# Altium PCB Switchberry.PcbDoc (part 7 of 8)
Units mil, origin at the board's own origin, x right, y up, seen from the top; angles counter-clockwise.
Board outline 4500 x 3824.8 mil, 6 copper layers (L01-TOP, L02-GND, L03-SIG, L04-SIG, L05-GND, L06-BOT), stack 49.214 mil thick; 431 components, 322 nets, 1699 pads, 1274 vias.
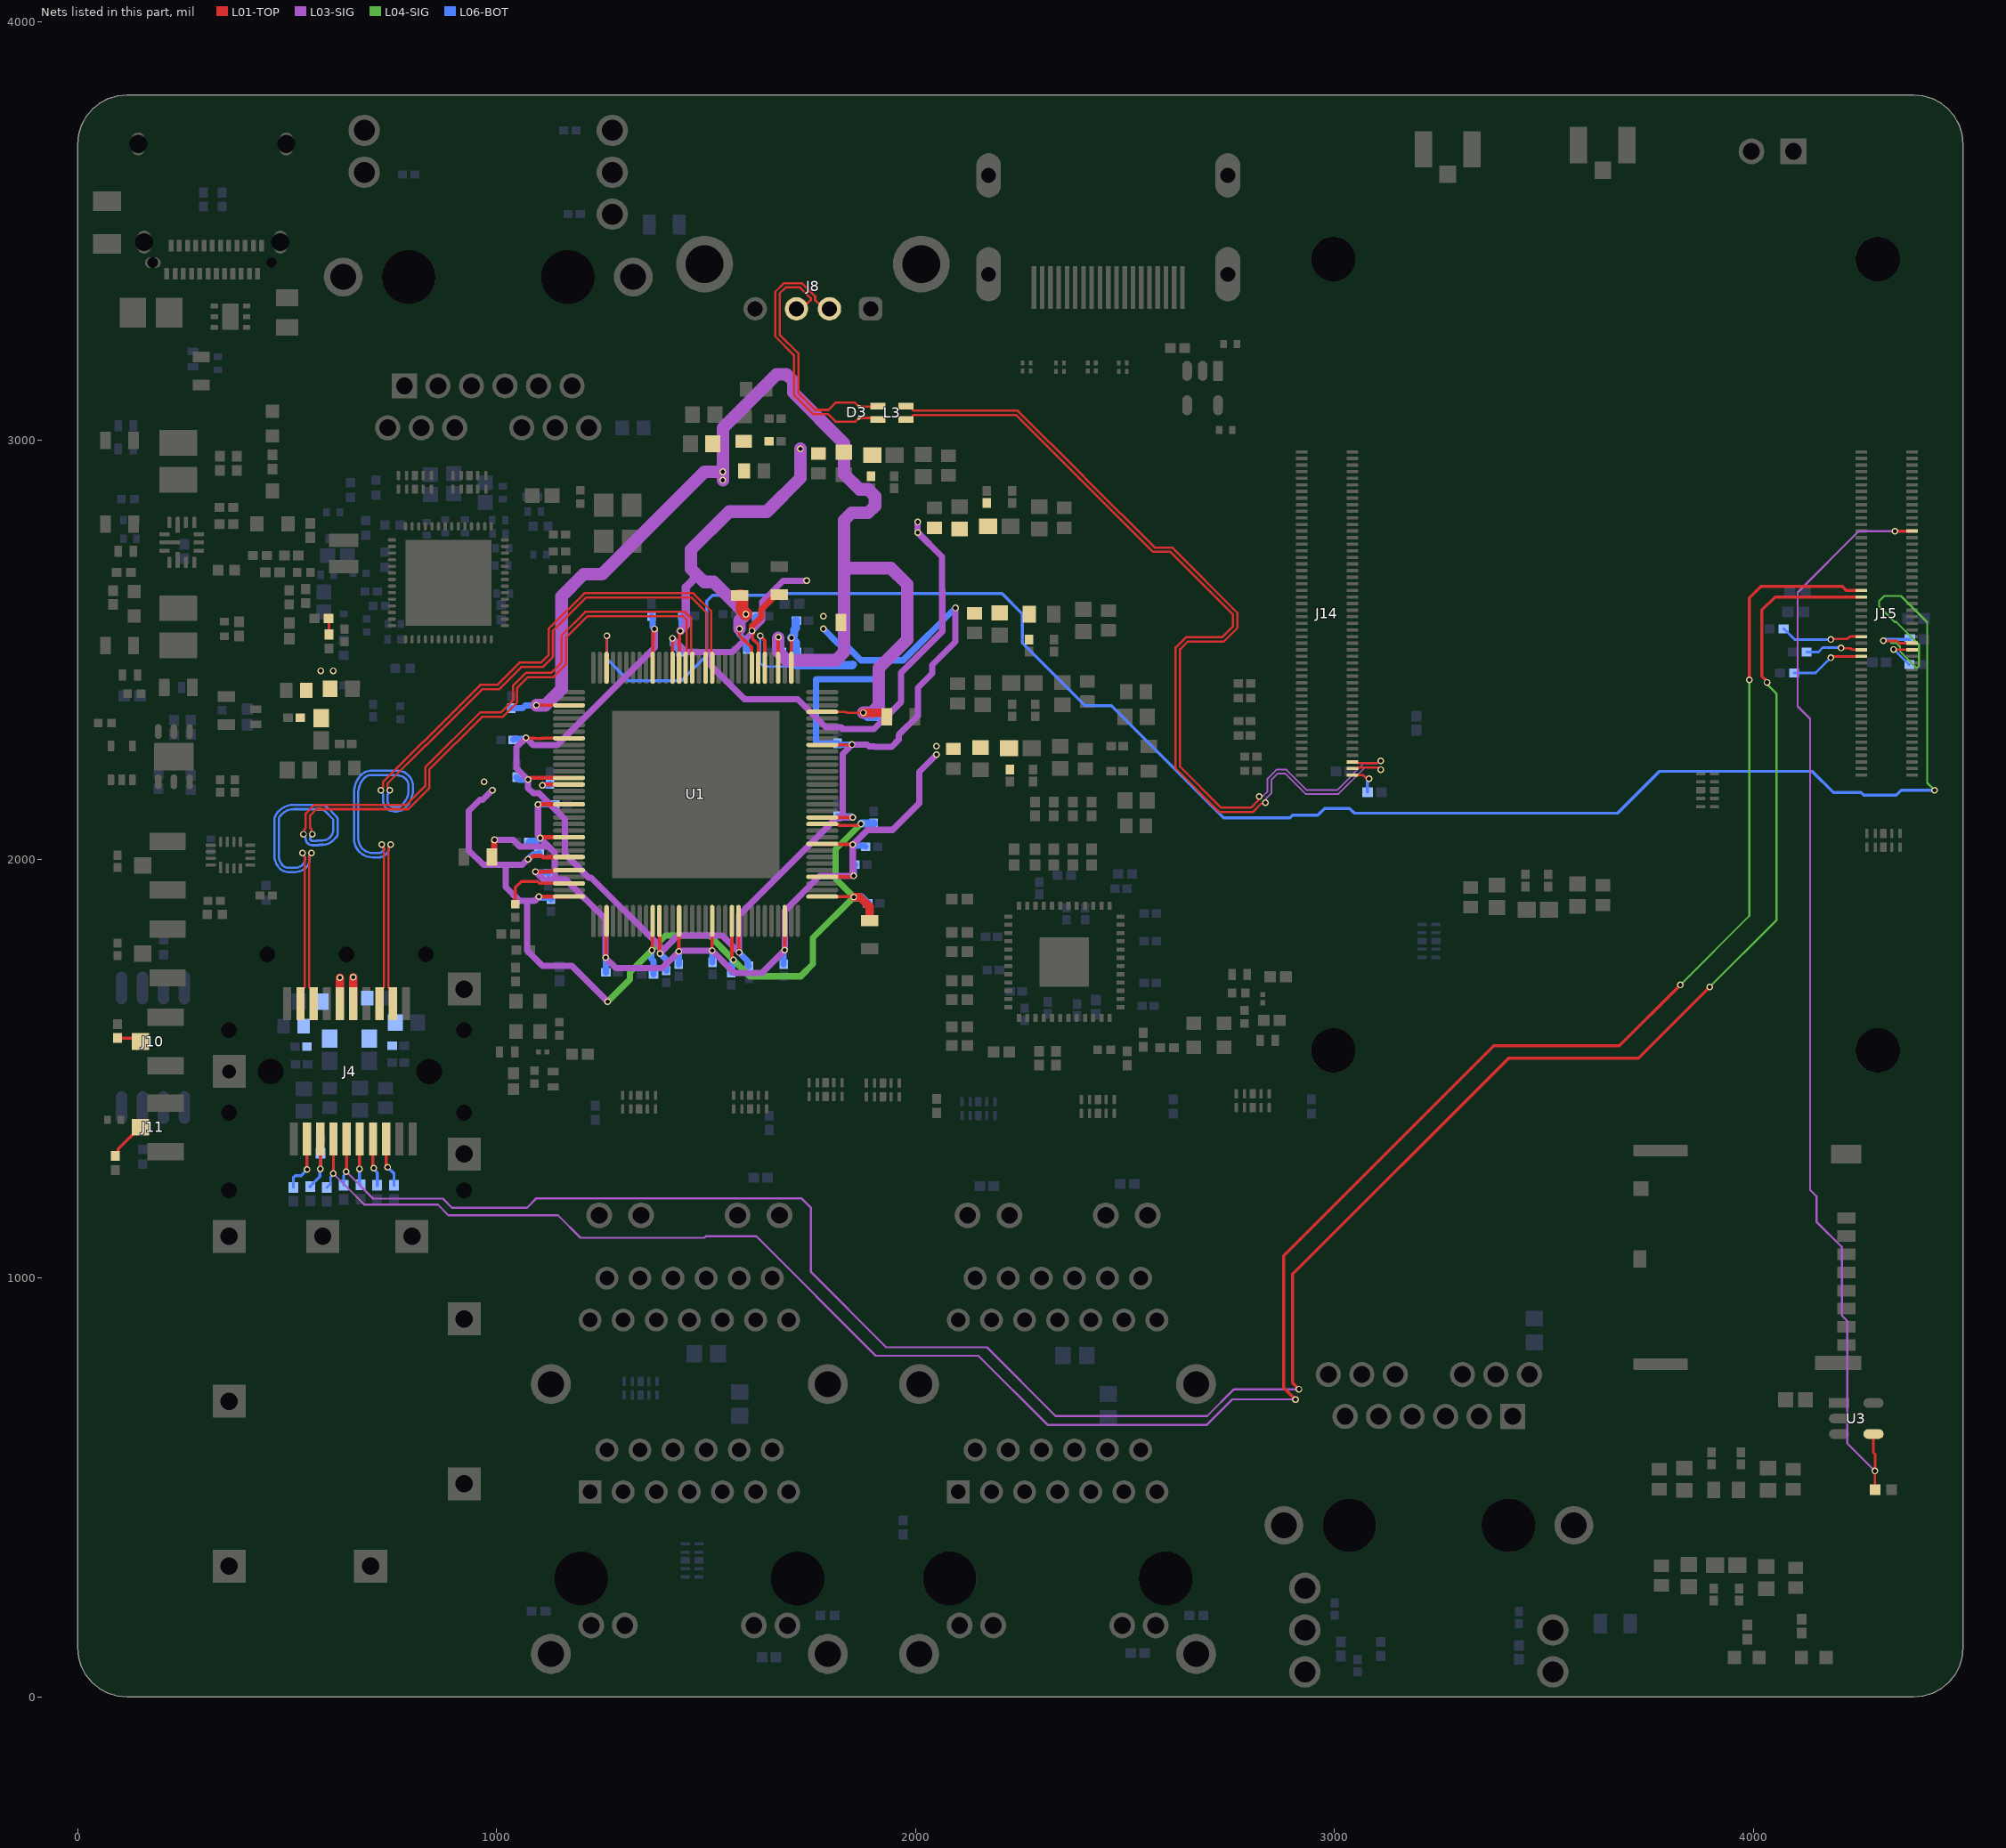
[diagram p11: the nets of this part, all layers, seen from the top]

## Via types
v1: diameter 16, hole 10, L01-TOP to L06-BOT, tented both sides, 1262 vias
v2: diameter 11.81, hole 7.87, L01-TOP to L06-BOT, tented both sides, 4 vias
v3: diameter 19.68, hole 7.87, L01-TOP to L06-BOT, tented both sides, 4 vias
v4: diameter 157.48, hole 110.24, L01-TOP to L06-BOT, tented both sides, 4 vias

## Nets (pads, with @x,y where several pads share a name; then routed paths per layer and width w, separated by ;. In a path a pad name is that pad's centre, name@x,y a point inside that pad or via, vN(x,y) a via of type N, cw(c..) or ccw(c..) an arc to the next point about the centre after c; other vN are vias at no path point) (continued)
SD_PWR_ON: J15.75 R28.1 U3.4 | length 2642.6
  L01-TOP w6: U3.4@4286.07,628.01 4286.07,583.93 4290,580 4290,540.27 v1(4289.54,539.82) 4289.54,495.77 R28.1@4290.31,495
  L01-TOP w7.27: v1(4337.32,2782.99) 4337.94,2783.6 J15.75@4377.9,2783.6
  L03-SIG w4.97: v1(4289.54,539.82) 4223.68,605.68 4223.68,897.64 4210.68,910.63 4210.68,1074.32 4150,1135 4150,1195.6 4135,1210.6 4135,2335 4105,2365 4105,2637.32 4250.66,2782.99 v1(4337.32,2782.99)
SFP1_FAULT: J4.2 R2.2 | length 136.8
  L01-TOP w7.27: J4.2@547.49,1332.05 547.49,1259.61 v1(547.72,1259.61)
  L06-BOT w7.27: R2.2@515,1216.73 515,1240 520,1245 533.12,1245 v1(547.72,1259.61)
SFP1_LOS: J4.8 R7.2 | length 120.1
  L01-TOP w7.27: J4.8@736.46,1332.05 736.46,1265 v1(740,1265)
  L06-BOT w7.27: v1(740,1265) 755,1250 R7.2@755,1221.73
SFP1_MOD_ABS: J4.6 R5.2 | length 110.8
  L01-TOP w7.27: v1(673,1261) 673,1332.05 J4.6@673.47,1332.05
  L06-BOT w7.27: v1(673,1261) 673,1224.76 R5.2@675.15,1222.61
SFP1_RATE_SELECT: J4.7 R6.2 | length 115.4
  L01-TOP w7.27: J4.7@704.97,1332.05 704.97,1262.53 v1(706.48,1262.53)
  L06-BOT w7.27: v1(706.48,1262.53) 706.48,1260.17 715,1251.65 R6.2@715,1221.73
SFP1_SCL: J4.5 J15.56 R4.2 | length 5553.9
  L01-TOP w7.27: v1(641.16,1254.13) 641.98,1254.13 J4.5@641.98,1332.05 ; v1(2915,735) 2900,750 2900,1009.49 3415.51,1525 3725,1525 v1(3895,1695) ; v1(4032,2422.28) 4032,2424.64 4020,2436.64 4020,2595 4051.06,2626.06 4256.58,2626.06 J15.56@4256.64,2626.12
  L03-SIG w4.97: v1(641.16,1254.13) 705.3,1189.99 871.87,1189.99 893.5,1168.36 1072.92,1168.36 1095.38,1190.82 1727.09,1190.82 1750.38,1167.53 1750.38,1014.49 1929.87,835 2170,835 2334.15,670.85 2695.85,670.85 2760,735 v1(2915,735)
  L04-SIG w4.97: v1(3895,1695) 4055,1855 4055,2395 4034.11,2415.89 4034.11,2420.17 v1(4032,2422.28)
  L06-BOT w6: R4.2@635,1221.73 635,1245.27 641.16,1251.43 v1(641.16,1254.13)
SFP1_SDA: J4.4 J15.58 R3.2 | length 5550
  L01-TOP w6: J15.58@4245.86,2642.8 4246.23,2642.77 J15.58@4256.64,2641.87
  L01-TOP w7.27: v1(610,1250) 610.48,1250 J4.4@610.48,1332.05 ; v1(2906.63,710) 2878.26,738.38 2878.26,1053.26 3380,1555 3680,1555 v1(3825,1700) ; v1(3990,2428.37) 3990,2623.37 4017.63,2651 4211.86,2651 4220.99,2641.87 J15.58@4256.64,2641.87
  L03-SIG w4.97: v1(610,1250) 684.53,1175.47 859.53,1175.47 885,1150 1146.54,1150 1200,1096.54 1496.23,1096.54 1500.18,1100.49 1619.51,1100.49 1905,815 2149.68,815 2314.68,650 2695,650 2755.84,710.84 2905.79,710.84 v1(2906.63,710)
  L04-SIG w4.97: v1(3825,1700) 3990,1865 v1(3990,2428.37)
  L06-BOT w6: R3.2@595,1216.73 603.81,1225.54 603.81,1241.1 610,1247.29 v1(610,1250)
SFP1_TXDISABLE: J4.3 R1.2 R8.1 | length 161.3
  L01-TOP w7.27: J4.3@578.98,1332.05 579.11,1332.05 v1(579.11,1261.07)
  L06-BOT w7.27: R1.2@555,1218.46 555,1219.45 577.71,1242.16 577.71,1259.67 v1(579.11,1261.07) 579.11,1297.38 R8.1@580,1298.27
SFP1_VCCR: C10.1 C11.2 C12.1 FB2.2 J4.15 | length 63.7
  L01-TOP w20: J4.15@657.72,1654.89 657.72,1718.37 v1(657.95,1718.37)
SFP1_VCCT: C4.1 C5.2 C6.1 FB1.2 J4.16 | length 62.8
  L01-TOP w20: J4.16@626.23,1654.89 v1@626.23,1717.64
  other v1: 626.19,1717.64
SFP_SW_N: J4.12 U1.78 | length 2155.5
  L01-TOP w5.38: v1(724,2165) 724,2167.87 729.31,2173.19 729.31,2185.37 825.02,2281.07 826.07,2281.07 961.17,2416.17 1001.17,2416.17 1054.4,2469.4 1105.73,2469.4 1123.98,2487.66 1123.98,2549.56 1209.8,2635.38 1469.3,2635.38 1511.69,2592.99 1511.69,2494.44 1514.37,2491.76 U1.78@1514.37,2457.18 ; v1(746.96,2035) cw(c740.03,2035) 744.93,2030.09 744.31,2029.47 ccw(c750.72,2023.06) 741.65,2023.06 741.65,1694.72 744.8,1691.57 745.06,1691.57 752.21,1684.42 J4.12@752.21,1654.89
  L06-BOT w5.38: v1(724,2165) ccw(c730.94,2165) 726.03,2160.09 cw(c718.12,2152.18) 729.31,2152.18 729.31,2138.82 ccw(c752.12,2138.82) 735.99,2122.69 ccw(c756.61,2143.25) 756.61,2114.14 761.43,2114.14 ccw(c761.43,2143.18) 781.97,2122.64 782,2122.68 ccw(c737.65,2167.04) 800.38,2167.04 800.38,2175.1 ccw(c766.09,2175.1) 799.45,2183.04 ccw(c766.09,2175.1) 790.34,2199.34 787.34,2202.34 ccw(c766.3,2181.3) 766.3,2211.05 698.68,2211.05 ccw(c698.68,2181.36) 677.68,2202.36 676.77,2201.45 ccw(c718.17,2160.05) 659.62,2160.05 659.62,2049.1 ccw(c704.03,2049.1) 672.63,2017.69 672.72,2017.6 ccw(c704.06,2048.94) 704.06,2004.62 719.25,2004.62 ccw(c719.25,2026.94) 735.03,2011.16 738.46,2014.59 ccw(c730.75,2022.3) 741.65,2022.3 741.65,2023.06 cw(c750.72,2023.06) 744.31,2029.47 v1@744.93,2030.09 ; v1@744.94,2030.1 ccw(c740.03,2035) v1(746.96,2035)
SFP_SW_P: J4.13 U1.79 | length 2022.8
  L01-TOP w5.38: J4.13@720.72,1654.89 720.72,1684.42 727.87,1691.57 728.13,1691.57 731.28,1694.72 731.28,2023.06 ccw(c722.21,2023.06) 728.62,2029.47 728,2030.09 cw(c732.9,2035) v1(725.96,2035) ; v1(745,2165) 745,2167.87 739.69,2173.19 739.69,2181.07 829.32,2270.7 830.37,2270.7 965.47,2405.79 1005.47,2405.79 1058.7,2459.02 1110.02,2459.02 1134.36,2483.36 1134.36,2545.26 1214.1,2625 1465,2625 1485,2605 1501.31,2588.69 1501.31,2494.44 1498.62,2491.76 U1.79@1498.62,2457.18
  L06-BOT w5.38: v1(725.96,2035) ccw(c732.9,2035) 727.99,2030.1 729.6,2028.49 cw(c725.56,2024.45) 731.28,2024.45 cw(c725.56,2024.45) 729.61,2020.42 727.73,2018.54 cw(c719.18,2027.09) 719.18,2015 704.14,2015 cw(c704.14,2049.14) 680,2025 cw(c704.14,2049.14) 670,2049.14 670,2160 cw(c718.28,2160) 684.14,2194.14 685,2195 cw(c698.7,2181.3) 698.7,2200.68 762.16,2200.68 cw(c762.16,2171.3) 782.93,2192.07 cw(c765.86,2175) 790,2175 790,2167.06 cw(c737.58,2167.06) 774.65,2130 cw(c761.4,2143.25) 761.4,2124.51 756.61,2124.51 cw(c756.61,2143.25) 743.36,2130 cw(c752.23,2138.87) 739.69,2138.87 739.69,2152.18 cw(c750.88,2152.18) 742.97,2160.09 ccw(c738.06,2165) v1(745,2165)
SPI0_CE0: J15.39 R44.2 | length 96.8
  L01-TOP w6: v1(4334,2501) 4334.43,2500.57 4377.46,2500.57 J15.39@4377.9,2500.13
  L06-BOT w6: v1(4334,2501) 4334.27,2501 4370.57,2464.7 R44.2@4371.55,2464.7
SPI0_CLK: J15.38 R45.1 | length 176.2
  L01-TOP w6: v1(4184,2481) 4187.39,2484.39 J15.38@4256.64,2484.39
  L06-BOT w6: R45.1@4096.73,2445 4148,2445 v1(4184,2481)
SPI0_MISO: J15.40 R47.1 | length 135.2
  L01-TOP w6: v1(4209,2504.39) ccw(c4212.03,2509.57) 4211.99,2503.57 4228.95,2503.57 cw(c4228.95,2497.57) 4232.65,2502.29 4233.22,2501.84 ccw(c4236.92,2506.57) 4236.92,2500.57 4245.86,2500.57 J15.40@4256.64,2500.13
  L06-BOT w6: R47.1@4126.73,2495 4155,2495 4165,2505 4208.39,2505 v1(4209,2504.39)
SPI0_MOSI: J15.44 R46.1 | length 197.9
  L01-TOP w6: v1(4184,2524.5) 4185.5,2526 4221.51,2526 ccw(c4221.51,2532) 4225.73,2527.73 ; 4225.74,2527.74 4227.89,2529.89 cw(c4232.12,2525.63) 4232.12,2531.63 J15.44@4256.64,2531.63
  L06-BOT w6: R46.1@4071.73,2550 4072.72,2550 4098.22,2524.5 v1(4184,2524.5)
SW_25MHz: C174.2 U1.126 | length 175.9
  L01-TOP w7.27: C174.2@1044.92,1893.04 1044.92,1933.13 1059.11,1947.32 1097.64,1947.32 1102.56,1942.4 U1.126@1172.82,1942.4
SW_AVDDH: C109.1 C110.2 C111.1 C112.1 C113.1 C114.1 C115.1 C116.1 C117.1 C118.1 C176.2 FB8.2 U1.10 U1.22 U1.33 U1.44 U1.111 U1.122 U1.128 | length 2783.8
  L01-TOP w5.38: v1(1370.49,1782.76) v1@1371.61,1783.89 ; U1.10@1371.61,1851.79 U1.10@1372.64,1852.82 ; v1@1851.46,1910.91 v1(1852.55,1909.81)
  L01-TOP w8: v1@1371.61,1783.89 U1.10@1371.61,1851.79 ; U1.22@1561.61,1852.82 1561.61,1766.26 1565,1762.87 v1(1565,1760) ; U1.33@1777.18,1910.91 v1@1851.46,1910.91 ; U1.44@1777.18,2084.13 1811.05,2084.13 1812.43,2082.75 1816.26,2082.75 1818.41,2080.6 1863.58,2080.6 1867.63,2084.64 v1(1869.79,2084.64)
  L01-TOP w10: v1(1075,2000) 1076.62,2000 1079.62,2003 1080.87,2003 1085.87,2008 1107.46,2008 1110.41,2005.05 1138.83,2005.05 1139.04,2005.25 1172.27,2005.25 U1.122@1172.47,2005.06 ; v1(1100.98,1910.56) 1101.32,1910.91 U1.128@1172.82,1910.91 ; v1(1109.35,2176.37) 1110.97,2176.37 1113.23,2178.62 U1.111@1172.82,2178.62
  L01-TOP w20: v1(1852.55,1909.81) 1867.12,1909.81 1890,1886.93 C176.2@1890,1853.46
  L03-SIG w15: v1(990,2165) 966.67,2141.67 959.92,2141.67 933.83,2115.58 933.83,2021.18 968.36,1986.65 1021.93,1986.65 ; v1(1075,2000) 1074.73,2000 1061.38,1986.65 1021.93,1986.65 ; v1(1100.98,1910.56) 1100.71,1910.56 1090.52,1900.37 1072.84,1900.37 ; v1(1265,1660) 1179.5,1745.5 1109.5,1745.5 1072.84,1782.16 1072.84,1900.37 ; 1021.93,1986.65 1021.93,1933.59 1055.15,1900.37 1072.84,1900.37
  L04-SIG w15: v1(1265,1660) 1317.74,1712.74 1317.74,1730.02 1370.68,1782.95 1370.68,1784.67 1403.51,1817.5 1508.04,1817.5 1536.43,1789.12 1536.43,1788.57 v1(1565,1760) 1604.39,1720.61 1725.61,1720.61 1755,1750 1755,1812.26 v1(1852.55,1909.81) 1808.9,1953.46 1808.9,2023.75 v1(1869.79,2084.64)
  L06-BOT w15: v1(1075,2000) 1075.27,2000 1087.69,2012.42 1098.64,2012.42 C117.1@1101.22,2015 ; v1(1100.98,1910.56) 1101.25,1910.56 1103.49,1908.33 1127.42,1908.33 1130,1905.75 C116.1@1130,1904.39 ; v1(1109.35,2176.37) 1109.54,2176.56 1124.95,2176.56 1127.53,2179.14 C118.1@1127.53,2179.98 ; v1(1370.49,1782.76) 1370.49,1782.49 1369.5,1781.5 1369.5,1762.47 1374.39,1757.58 C115.1@1374.39,1725 ; C114.1@1560,1729.39 1562.58,1731.97 1562.58,1757.31 1565,1759.73 v1(1565,1760)
  L06-BOT w20: v1(1852.55,1909.81) 1869.44,1909.81 1884.25,1895 C113.1@1885.61,1895 ; v1(1869.79,2084.64) 1870.76,2085.61 C112.1@1900,2085.61
  other v1: 970,2185 580,2450 610,2450
SW_AVDDL: C122.1 C123.2 C124.1 C125.1 C126.1 C127.1 C128.1 C129.1 C130.1 C131.1 C132.1 C133.1 C177.2 FB9.2 U1.3 U1.14 U1.19 U1.30 U1.36 U1.41 U1.114 U1.119 U1.124 | length 2862.2
  L01-TOP w5.38: v1(1260,1765) v1@1261.38,1766.38 ; U1.3@1261.38,1851.79 U1.3@1262.4,1852.82 ; v1(1435,1780) v1@1435.31,1780.31 ; U1.14@1435.31,1852.5 U1.14@1435.63,1852.82 ; v1@1514.37,1782.18 v1(1514.56,1781.99) ; v1(1687.47,1783.04) v1@1687.6,1783.16
  L01-TOP w8: v1@1261.38,1766.38 U1.3@1261.38,1851.79 ; v1@1435.31,1780.31 U1.14@1435.31,1852.5 ; v1@1514.37,1782.18 U1.19@1514.37,1852.82 ; v1@1687.6,1783.16 U1.30@1687.6,1852.82 ; U1.36@1777.18,1958.15 1850.22,1958.15 v1(1852.38,1960.31) ; U1.41@1777.18,2036.89 1778.13,2035.94 1849.06,2035.94 v1(1850,2035)
  L01-TOP w10: v1(1092.9,1970.15) 1129.96,1970.15 1133.33,1973.51 1139.11,1973.51 1139.49,1973.9 U1.124@1172.82,1973.9 ; v1(1098.77,2130.83) 1099.05,2131.1 1172.54,2131.1 U1.114@1172.82,2131.38 ; v1(1104.33,2050.72) 1105.95,2050.72 1107.87,2052.64 U1.119@1172.82,2052.64
  L01-TOP w15: C177.2@988.46,2005 993.76,2010.3 993.76,2044.79 995.04,2046.07 v1(995.04,2046.34)
  L03-SIG w15: v1(995.04,2046.34) 1039.5,2046.34 1055.09,2030.75 1124.31,2030.75 ; v1(1092.9,1970.15) 1093.17,1970.15 1111.98,1951.34 1138.74,1951.34 ; v1(1098.77,2130.83) 1098.77,2056.55 1104.33,2050.99 v1(1104.33,2050.72) 1124.31,2030.75 ; v1(2050,2250) 2008.81,2208.81 2008.81,2133.86 1945.18,2070.23 1885.23,2070.23 v1(1850,2035) 1850,1962.96 1852.38,1960.58 v1(1852.38,1960.31) 1771.07,1960.31 1687.67,1876.91 1687.67,1783.23 v1(1687.47,1783.04) 1633.32,1728.89 1567.12,1728.89 1535.96,1760.05 1535.96,1760.32 1514.56,1781.72 v1(1514.56,1781.99) 1437.26,1781.99 1435.27,1780 v1(1435,1780) 1394.87,1739.87 1285.13,1739.87 v1(1260,1765) 1260,1856.85 1165.5,1951.34 1138.74,1951.34 ; 1124.31,2030.75 1138.74,2016.31 1138.74,1951.34
  L06-BOT w5.38: C132.1@1070.55,2039.73 cw(c1074.45,2035.83) 1074.45,2041.34 C132.1@1076.64,2041.34
  L06-BOT w15: C132.1@1076.64,2041.34 1079.23,2043.92 1097.26,2043.92 1104.06,2050.72 v1(1104.33,2050.72) ; v1(1092.9,1970.15) 1093.17,1970.15 1094.24,1969.08 1120.92,1969.08 1123.5,1966.5 C131.1@1123.5,1965.14 ; v1(1098.77,2130.83) 1098.91,2130.96 1139.17,2130.96 C133.1@1139.31,2131.1 ; v1(1260,1765) 1260,1764.73 1260.61,1764.12 C130.1@1260.61,1730 ; C129.1@1435,1749.39 v1(1435,1780) ; v1(1514.56,1781.99) 1514.75,1781.8 1514.75,1754.64 C128.1@1515,1754.39 ; C127.1@1685,1749.39 1685,1780.29 1687.47,1782.77 v1(1687.47,1783.04) ; v1(1850,2035) 1850.27,2035 1852.69,2032.58 1878.03,2032.58 C125.1@1880.61,2030 ; v1(1852.38,1960.31) 1852.57,1960.5 1852.57,1984.38 1855.15,1986.96 C126.1@1855.39,1986.96
  other v1: 2050,2270
SW_DVDDL: C137.1 C138.2 C139.1 C140.1 C141.1 C142.1 C143.1 C144.1 C145.1 C146.1 C147.1 C148.1 C178.2 R93.2 U1.11 U1.23 U1.45 U1.56 U1.66 U1.70 U1.87 U1.104 U1.110 | length 4691.5
  L01-TOP w5.38: U1.11@1388.39,1852.82 U1.11@1389.19,1852.01 ; v1@1389.19,1775.81 v1(1390,1775) ; U1.23@1577.36,1852.82 U1.23@1578,1852.18 ; v1@1578,1778.28 v1(1578.64,1777.64)
  L01-TOP w8: v1(1070,2290) 1071.14,2288.86 1092.1,2288.86 1092.96,2288 1107.04,2288 1107.9,2288.86 U1.104@1172.82,2288.86 ; U1.87@1372.99,2457.54 1372.99,2526.83 1373.71,2527.55 1373.71,2541.18 1375.23,2542.69 1375.23,2548.34 v1(1376.76,2549.87) ; v1@1389.19,1775.81 U1.11@1389.19,1852.01 ; v1@1578,1778.28 U1.23@1578,1852.18 ; v1(1629.3,2533.7) 1629.3,2533.04 1640.32,2522.01 U1.70@1640.35,2457.18 ; U1.66@1703.35,2457.18 1703.51,2457.35 1703.51,2528.44 v1(1703.67,2528.6) ; U1.45@1777.18,2099.88 1777.24,2099.94 v1(1850,2100) v1(1850,2100) ; U1.56@1777.18,2273.11 1847.55,2273.11 v1(1848.19,2273.75)
  L01-TOP w10: v1(1075,2190) 1077.87,2190 1082.24,2194.37 U1.110@1172.82,2194.37
  L03-SIG w15: v1(1376.76,2549.87) 1377.21,2549.41 1377.21,2505.6 1144.69,2273.08 1087.19,2273.08 1070.27,2290 v1(1070,2290) 1047.51,2267.51 1047.51,2217.49 v1(1075,2190) 1075.19,2189.81 1075.19,2169.84 1087.34,2157.69 1100.9,2157.69 1163.52,2095.07 1163.52,2012.58 1219.77,1956.32 1225.91,1956.32 1390.99,1791.25 1390.99,1776.26 1390,1775.27 v1(1390,1775) 1432.5,1817.5 1538.78,1817.5 v1(1578.64,1777.64) 1578.64,1866.18 1812.46,2100 1829.49,2100 ; v1@1849.81,2099.81 v1(1850,2100) 1829.49,2100 ; v1(2095,2600) 2095,2519.29 2039.5,2463.79 2039.5,2444.05 2005.45,2410 2005.45,2343.12 1959.83,2297.5 1959.83,2285.84 1942.6,2268.61 1902.44,2268.61 1901.61,2269.44 1888.54,2269.44 1884.23,2273.75 v1(1848.19,2273.75) 1826.13,2251.69 1826.13,2103.36 1829.49,2100
  L06-BOT w5.38: v1(1629.3,2533.7) 1629.3,2468.24 1638.11,2459.43 1642.57,2459.43 1643.14,2460 1715.61,2460
  L06-BOT w15: C141.1@1039.39,2285 1041.97,2287.58 1067.31,2287.58 1069.73,2290 v1(1070,2290) ; C148.1@1047.51,2196.19 1047.51,2194.84 1050.09,2192.25 1051.45,2192.25 1053.51,2190.19 1074.81,2190.19 v1(1075,2190) ; C142.1@1370,2580.61 1370,2579.25 1372.58,2576.67 1372.58,2554.31 1376.76,2550.14 v1(1376.76,2549.87) ; v1(1390,1775) 1405,1760 C147.1@1405,1734.39 ; v1(1578.64,1777.64) 1578.64,1777.37 1599.43,1756.58 1599.43,1747.25 C146.1@1602.01,1744.67 ; v1(1780,2550) 1814.64,2515.36 1829.57,2515.36 1869.93,2475 1970,2475 v1(2095,2600) ; C145.1@1813.74,2102.89 1846.83,2102.89 1849.73,2100 v1(1850,2100) ; v1(1848.19,2273.75) 1848,2273.95 1816.68,2273.95 1814.1,2276.53 C144.1@1814.1,2276.9 1761.98,2276.9 1761.98,2430 1920,2430 1920,2455
  L06-BOT w20: C140.1@1715.61,2570 1714.25,2570 1714.17,2569.92 1714.17,2551.7 1710.23,2547.76 1710.23,2535.16 v1(1703.67,2528.6) 1714.17,2518.11 1714.17,2495.08 1714.25,2495 C143.1@1715.61,2495 1715.61,2463.49 1848.49,2463.49 1850,2465
  other v1: 1780,2580
SW_GPIO_1: J10.1 R49.2 | length 58.4
  L01-TOP w7.27: R49.2@95,1573.27 141.69,1573.27 J10.1@149.96,1565
SW_INTR_N: J15.41 R41.1 U1.94 | length 4841.8
  L01-TOP w6: U1.94@1262.4,2457.18 1262.4,2532.9 v1(1263.01,2533.51) ; v1(4309.51,2521.51) 4310.01,2521 4342.28,2521 4347.4,2515.88 J15.41@4377.9,2515.88
  L04-SIG w4.97: v1(4309.51,2521.51) 4324.06,2521.51 4329.08,2516.49 4340.41,2516.49 4349.49,2507.41 4349.49,2496.08 4387.27,2458.3 4391.39,2458.3 4394.3,2461.21 4394.3,2512.6 4340.41,2566.49 4336.62,2566.49 4299.51,2603.59 4299.51,2616.41 4311.59,2628.49 4351.41,2628.49 4414.24,2565.66 4414.24,2182.48 v1(4431.72,2165)
  L06-BOT w7.27: v1(1263.01,2533.51) 1263.01,2477.83 1315.01,2425.83 1441.27,2425.83 1498.62,2483.18 ; 1502.11,2486.67 1498.62,2483.18 ; v1(4309.51,2521.51) 4311.87,2521.51 4315.36,2525 R41.1@4373.27,2525 ; v1(4431.72,2165) 4351.81,2165 4340.19,2153.38 4262.64,2153.38 4256.22,2159.8 4190.2,2159.8 4140,2210 3775,2210 3675,2110 3047.65,2110 3036.01,2121.63 2976.32,2121.63 2959.69,2105 2900,2105 2893.76,2098.76 2735.35,2098.76 2467.48,2366.63 2404.84,2366.63 2255.2,2516.28 2255.2,2585.69 2206.49,2634.4 1675.85,2634.4 1671.45,2630 1515,2630 1501.31,2616.31 1501.31,2485.87 1498.62,2483.18
SW_RST_N: R43.2 R75.1 | length 38.8
  L01-TOP w7.27: R75.1@598.93,2575.09 600,2574.03 R43.2@600,2536.73
SW_SFP_N: J4.19 U1.82 | length 2165.9
  L01-TOP w5.38: J4.19@531.74,1654.89 531.74,1684.42 538.89,1691.57 539.15,1691.57 542.3,1694.72 542.3,1758.16 542.3,2003.06 ccw(c533.23,2003.06) 539.64,2009.47 539.02,2010.09 cw(c543.93,2015) v1(536.99,2015) ; v1(560.31,2060) 558.28,2062.03 558.28,2071.72 555,2075 555,2105 569.62,2119.62 789.3,2119.62 840,2170.32 840,2215 965,2340 1014.61,2340 1049.31,2374.7 1049.31,2409.63 1074.68,2435 1135.28,2435 1165.38,2465.1 1165.38,2529.12 1216.26,2580 1445,2580 1454.06,2570.94 1454.06,2494.44 1451.38,2491.76 U1.82@1451.38,2457.18
  L06-BOT w5.38: v1(536.99,2015) ccw(c543.93,2015) 539.02,2010.09 539.64,2009.47 cw(c533.23,2003.06) 542.3,2003.06 542.3,1999.56 cw(c524.78,1999.56) 537.17,1987.17 537.07,1987.07 cw(c520,2004.14) 520,1980 502.07,1980 cw(c502.07,1997.07) 490,1985 cw(c514.14,2009.14) 480,2009.14 480,2092.93 cw(c497.07,2092.93) 485,2105 488.75,2108.75 cw(c515,2082.5) 515,2119.62 580.38,2119.62 cw(c580.38,2107.56) 588.91,2116.09 610,2095 610,2071.21 cw(c582.93,2071.21) 602.07,2052.07 cw(c585,2069.14) 585,2045 572.69,2045 ccw(c572.69,2043.18) 571.4,2044.47 cw(c570.11,2045.75) 570.11,2043.93 560.38,2043.93 cw(c560.38,2049.31) 556.58,2045.51 cw(c560.38,2049.31) 555,2049.31 555,2049.45 cw(c560.71,2049.45) 556.66,2053.48 558.28,2055.09 ccw(c553.37,2060) v1(560.31,2060)
SW_SFP_P: J4.18 U1.81 | length 2299.7
  L01-TOP w5.38: v1(539.31,2060) 541.34,2062.03 541.34,2071.72 544.62,2075 544.62,2109.3 565.32,2130 785,2130 829.62,2174.62 829.62,2219.3 960.7,2350.38 1010.31,2350.38 1038.93,2379 1038.93,2413.93 1070.38,2445.38 1130.98,2445.38 1155,2469.4 1155,2533.42 1211.96,2590.38 1449.3,2590.38 1452.34,2587.34 1464.44,2575.24 1464.44,2494.44 1467.13,2491.76 U1.81@1467.13,2457.18 ; v1(557.99,2015) cw(c551.05,2015) 555.96,2010.09 555.33,2009.47 ccw(c561.74,2003.06) 552.68,2003.06 552.68,1753.86 552.68,1694.72 555.83,1691.57 556.08,1691.57 563.24,1684.42 J4.18@563.24,1654.89
  L06-BOT w5.38: v1(539.31,2060) ccw(c546.25,2060) 541.34,2055.09 541.43,2055.01 cw(c533.72,2047.3) 544.62,2047.3 ccw(c555.52,2047.3) 547.81,2039.6 549.24,2038.17 ccw(c560.38,2049.31) 560.38,2033.56 574.41,2033.56 ccw(c574.41,2035.38) 575.7,2034.09 cw(c576.98,2032.8) 576.98,2034.62 585.07,2034.62 ccw(c585.07,2068.98) 609.36,2044.68 617.34,2052.66 ccw(c610,2060) 620.38,2060 620.38,2095.04 ccw(c610.1,2095.04) 617.37,2102.31 ; v1(557.99,2015) cw(c551.05,2015) 555.96,2010.09 555.33,2009.47 ccw(c561.74,2003.06) 552.68,2003.06 552.68,1995.55 cw(c534.45,1995.55) 547.34,1982.66 544.41,1979.73 cw(c520,2004.14) 520,1969.62 502.07,1969.62 cw(c502.07,1997.07) 482.66,1977.66 cw(c514.14,2009.14) 469.62,2009.14 469.62,2092.99 cw(c496.92,2092.99) 477.62,2112.3 481.44,2116.12 cw(c514.95,2082.61) 514.95,2130 580.46,2130 cw(c580.46,2107.76) 596.19,2123.49 617.37,2102.31
SW_VDDHS: C152.1 C153.2 C154.1 C155.1 C156.1 C179.2 FB10.2 U1.72 U1.83 | length 1158.8
  L01-TOP w8: U1.83@1436.13,2457.69 1436.13,2519.81 1436.82,2520.5 v1@1436.82,2537.79 ; v1@1436.84,2537.81 1436.84,2543.47 v1(1438.37,2545) ; v1(1579.63,2550.09) 1580.22,2549.5 1580.22,2534.03 1608.86,2505.38 U1.72@1608.86,2457.18
  L01-TOP w30: C179.2@1580,2630 1583.46,2630 1585.67,2627.8 1585.67,2594.33 v1(1595,2585)
  L03-SIG w20: v1(1438.37,2545) 1451.39,2558.01 1451.39,2649.4 1479.8,2677.8
  L03-SIG w30: v1(1579.63,2550.09) 1579.63,2569.63 v1(1595,2585) 1518.06,2661.94 1495.66,2661.94 1479.8,2677.8 1463.93,2693.67 1463.93,2738.93 1555,2830 1645,2830 1725,2910 v1(1725,2980)
  L06-BOT w15: v1(1438.37,2545) 1438.37,2545.27 1441.81,2548.71 1441.81,2579.1 C156.1@1444,2581.29 ; v1(1579.63,2550.09) 1579.5,2549.97 1579.5,2536.51 1595.45,2520.56 1595.45,2502.58 1598.03,2500 C155.1@1599.39,2500
SW_VDDIO: C168.1 C169.2 C170.1 C171.1 C172.1 C173.1 C181.2 R94.2 U1.61 U1.68 U1.99 | length 3136.9
  L01-TOP w5.38: v1(1095,2367.76) v1@1095.08,2367.68 ; U1.99@1172.74,2367.68 U1.99@1172.82,2367.6 ; U1.61@1777.18,2351.85 1834.03,2351.85 1835.88,2350 v1(1875,2350)
  L01-TOP w8: v1@1095.08,2367.68 U1.99@1172.74,2367.68 ; U1.68@1671.85,2457.18 1672.07,2457.41 1672.07,2529.78 v1(1672.3,2530)
  L01-TOP w20: v1(1875,2350) 1928.74,2350 1931.54,2347.2 C181.2@1931.54,2340
  L03-SIG w30: v1(1095,2367.76) 1116.61,2367.76 1155,2406.15 1155,2627.51 1207.97,2680.49 1251.73,2680.49 1496.24,2925 v1(1540,2925) ; v1(1540,2905) v1(1540,2925) ; v1@1672.36,2528.14 1672.07,2527.85 1672.07,2495.45 1692.52,2475 1810,2475 1829.57,2494.57 1829.57,2695 ; v1@1875.22,2350.17 1875.39,2350 1895.13,2350 1912.22,2367.09 1912.22,2456.6 1980.33,2524.71 1980.33,2655.86 1941.19,2695 1829.57,2695 ; v1(1540,2925) 1540,3029.6 1668.4,3158 1691.6,3158 1708,3141.6 1708,3113.93 1829.57,2992.36 1829.57,2920.03 1866.6,2883 1886.6,2883 1903,2866.6 1903,2843.4 1886.6,2827 1847.14,2827 1829.57,2809.43 1829.57,2695
  L06-BOT w15: C172.1@1035,2360.61 1061.62,2360.61 1068.57,2367.56 1094.81,2367.56 v1(1095,2367.76) ; v1(1672.3,2530) 1677.95,2524.34 1677.95,2495.08 1678.03,2495 C173.1@1679.39,2495
  L06-BOT w20: v1(1875,2350) 1884.92,2340.08 1905.53,2340.08 C171.1@1905.61,2340
SW_VDDLS: C160.1 C161.2 C162.1 C163.1 C164.1 C180.2 FB11.2 U1.71 U1.84 | length 1867.7
  L01-TOP w5.38: v1(1609.35,2545.65) v1@1610.66,2544.34
  L01-TOP w8: U1.84@1419.88,2457.18 v1@1419.85,2527.51 ; v1@1610.66,2544.34 1610.66,2526.89 1624.61,2512.95 U1.71@1624.61,2457.18
  L01-TOP w15: v1(1609.35,2545.65) 1609.54,2545.84 1609.54,2556.38 1632.05,2578.88 1632.05,2596.46 1667.13,2631.54 C180.2@1675,2631.54
  L03-SIG w15: v1(1419.82,2527.54) 1452.92,2494.44 1513.03,2494.44 ; v1(1740,2665) 1683.62,2665 1633.66,2615.04 1633.66,2569.96 v1(1609.35,2545.65) 1609.16,2545.46 1609.16,2540.73 1562.87,2494.44 1513.03,2494.44 ; v1(2005,2805) v1(2005,2780) 2062.63,2722.37 2062.63,2644.69 2063.49,2643.83 2063.49,2543.49 1965.67,2445.67 1965.67,2375.85 1900.55,2310.73 1826.61,2310.73 1822.44,2314.9 1786,2314.9 1718.75,2382.15 1591.77,2382.15 1513.03,2460.9 1513.03,2494.44
  L06-BOT w15: v1(1419.82,2527.54) 1420.01,2527.35 1420.01,2512.74 1438.31,2494.44 C163.1@1439.67,2494.44 ; v1(1609.35,2545.65) 1609.54,2545.84 1609.54,2546.61 1616.67,2553.74 1616.67,2577.42 1619.25,2580 C164.1@1620.61,2580
SYNCLKO: J11.1 R48.1 | length 105.4
  L01-TOP w7.27: R48.1@90,1291.73 97.19,1298.92 97.19,1308.22 148.98,1360 J11.1@149.96,1360 J11.1@141.69,1351.73
USB_FILT_N: D3.2 J8.2 L3.1 | length 664.7
  L01-TOP w5.38: J8.2@1794.37,3314.17 1780.99,3314.17 1760.19,3334.98 1760.19,3343.73 1728.54,3375.38 1685.7,3375.38 1665.15,3354.83 1665.15,3248.27 1709.62,3203.81 1709.62,3108.39 1755.7,3062.31 1791.62,3062.31 1808.93,3045 1856.38,3045 D3.2@1864.94,3053.56 1906.44,3053.56 L3.1@1910,3050
USB_FILT_P: D3.3 J8.3 L3.4 | length 612.6
  L01-TOP w5.38: J8.3@1715.63,3314.17 1729.01,3314.17 1749.81,3334.98 1749.81,3339.43 1724.24,3365 1690,3365 1675.53,3350.53 1675.53,3252.57 1720,3208.1 1720,3112.69 1760,3072.69 1791.62,3072.69 1808.93,3090 1855.27,3090 D3.3@1864.94,3080.33 1908.84,3080.33 L3.4@1910,3081.5
USB_N: J14.3 L3.2 | length 2172
  L01-TOP w5.38: L3.2@1976.93,3050 1986.77,3050 1991.96,3055.19 1991.96,3057.41 1995.11,3060.56 2239.44,3060.56 2390,2910 2566.17,2733.83 2607.73,2733.83 2757.56,2584 2757.56,2556.65 2730.91,2530 2645.32,2530 2620.66,2505.34 2620.66,2216.79 2721.91,2115.55 2724.95,2112.51 2804.69,2112.51 2825.31,2133.12 2832.82,2133.12 v1(2834.85,2135.15) ; J14.3@3042.46,2216.67 3052.31,2216.67 3054.99,2219.35 3101.81,2219.35 3107.13,2214.04 v1(3110,2214.04)
  L03-SIG w4.04: v1(2834.85,2135.15) 2836.52,2136.83 2836.52,2145.28 2849.04,2157.8 2849.04,2189.04 2865,2205 2881.43,2205 2903.49,2182.95 2930.48,2155.96 3009.38,2155.96 3073.44,2220.02 3101.65,2220.02 3107.63,2214.04 v1(3110,2214.04)
USB_OTG: J14.1 R9.2 | length 76.9
  L01-TOP w6: J14.1@3042.46,2200.92 3068.47,2200.92 3077.13,2192.26 v1(3082,2192.26)
  L06-BOT w7.27: R9.2@3078.27,2160 3078.27,2186.16 3082,2189.9 v1(3082,2192.26)
USB_P: J14.5 L3.3 | length 2170.9
  L01-TOP w5.38: L3.3@1976.93,3081.5 1986.77,3081.5 1991.96,3076.31 1991.96,3074.09 1995.11,3070.94 2243.74,3070.94 2397.34,2917.34 2407.61,2907.07 2570.47,2744.21 2612.03,2744.21 2767.94,2588.3 2767.94,2552.35 2735.21,2519.62 2649.62,2519.62 2631.04,2501.04 2631.04,2221.09 2729.25,2122.88 2800.4,2122.88 2817.97,2140.46 2817.97,2147.97 v1(2820,2150) ; J14.5@3042.46,2232.42 3052.31,2232.42 3054.99,2229.73 3101.81,2229.73 3107.13,2235.04 v1(3110,2235.04)
  L03-SIG w4.04: v1(2820,2150) 2821.68,2151.68 2830.13,2151.68 2840,2161.55 2840,2192.79 2861.25,2214.04 2885.18,2214.04 2934.22,2165 3005.63,2165 3069.7,2229.07 3101.65,2229.07 3107.63,2235.04 v1(3110,2235.04)
pads on no net: J1. J2. J3. J4.MH1 J4.MH2 J7.14 J9. J9.A2 J9.A3 J9.A6 J9.A7 J9.A8 J9.A10 J9.A11 J9.B2 J9.B3 J9.B6 J9.B7 J9.B8 J9.B10 J9.B11 J14.4 J14.6 J14.11 J14.15 J14.17 J14.21 J14.23 J14.27 J14.28 J14.29 J14.30 J14.33 J14.34 J14.35 J14.36 J14.39 J14.40 J14.41 J14.42 J14.43 J14.45 J14.46 J14.47 J14.48 J14.49 J14.52 J14.54 J14.57 J14.58 J14.59 J14.60 J14.63 J14.64 J14.65 J14.66 J14.69 J14.71 J14.75 J14.77 J14.81 J14.83 J14.87 J14.89 J14.93 J14.94 J14.95 J14.96 J15.20 J15.29 J15.30 J15.31 J15.34 J15.35 J15.36 J15.37 J15.46 J15.48 J15.49 J15.64 J15.68 J15.70 J15.72 J15.73 J15.76 J15.80 J15.82 J15.89 J15.91 J15.92 J15.94 J15.96 J15.99 J15.100 J17. SD1.9 SD1.10 U1.50 U1.51 U1.59 U1.60 U1.73 U1.74 U1.93 U1.108 U1.125 U3.3 U4.13 U4.43 U4.45 U4.47 U23.3@935,2883.56 U23.8@935,2916.44 U24.3@805,2883.56 U24.8@805,2916.44

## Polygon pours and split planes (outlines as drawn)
SW_AVDDH on L04-SIG "NONET_L-01_P-001" (solid, remove dead copper, pour order 86): 1249.51,1684.51 1422.53,1857.53 1612.53,1857.53 1655,1900 1655,2022.01 1780.12,2147.13 1876.59,2147.13 1894.02,2129.7 1894.02,1690.43 1846.59,1643 1257,1643 1249.51,1650.49
SW_AVDDH on L04-SIG "NONET_L-01_P-001" (solid, remove dead copper, pour order 10): 533.26,2484.56 533.26,2291.74 743.55,2081.45 1124.35,2081.45 1156.48,2113.58 1156.48,2237.73 1139.21,2255 935,2255 705,2485 637.39,2485
P3V3 on L04-SIG "NONET_L-01_P-001" (solid, remove dead copper, pour order 40): 1601.79,2844.62 1881.23,2844.62 2005.38,2720.47 2875.13,2720.47 4182.28,2720.47 4182.28,2930 2450.32,2930 2185.32,3195 1600,3195
P3V3 on L04-SIG "NONET_L-01_P-001" (solid, remove dead copper, pour order 70): 565,2903.43 875.7,3214.13 1700.87,3214.13 1775,3140 1775,2865 1754.62,2844.62 1310.18,2844.62 925.89,2460.33 665,2460.33 665,2453.58 638.24,2426.83
P3V3 on L04-SIG "NONET_L-01_P-001" (solid, remove dead copper, pour order 61): 953.96,1340 3845,1340 4381.89,803.11 4381.89,456.89 3990,65 391.25,65 208.25,248
P3V3 on L04-SIG "NONET_L-01_P-001" (solid, remove dead copper, pour order 60): 675,2255 1172.71,2255 1172.71,1285 652.72,1285 652.72,1374.63
P3V3 on L04-SIG "NONET_L-01_P-001" (solid, remove dead copper, pour order 59): 675,2505 675,2255 985.38,1944.62 985.38,255.38 855,125 330,125 52.49,402.51 52.49,2456.81 194.6,2598.92
P3V3 on L04-SIG "NONET_L-01_P-001" (solid, remove dead copper, pour order 58): 110,2514.32 194.6,2598.92 363.92,2598.92 530,2765 530,2890 550,2910 675,2910 800,2785 800,2545 760,2505 675,2505 675,2345 635,2305 140,2305 110,2335
P5V on L04-SIG "NONET_L-01_P-001" (solid, remove dead copper, pour order 57): 235,3267.5 235,3625.97 316.55,3707.52 3877.48,3707.52 4425,3160 4425,2776 4059.95,2776 3805.95,3030 2925,3030 2858.65,2963.65 2466.35,2963.65 2220.37,3209.63 889.63,3209.63 620,2940 490,2940
P5V on L04-SIG "NONET_L-01_P-001" (solid, remove dead copper, pour order 56): 235,3267.5 235,3035 125,2925 125,2683.41 194.6,2613.81 371.54,2613.81 513.91,2756.18 513.91,3464.25 394.09,3464.25
P5V on L04-SIG "NONET_L-01_P-001" (solid, remove dead copper, pour order 54): 235,3464.96 423.62,3464.96 423.62,3235 235,3235 235,3300
CHASSIS_GND on L04-SIG "NONET_L-01_P-001" (solid, remove dead copper, pour order 53): 3530,1110 3695,945 3695,165 3600,70 995,70 995,1110
GND on L02-GND "NONET_L-01_P-001" (solid, remove dead copper, pour order 12): -145,3870 4620,3870 4620,-90 -140,-90 -140,3615
GND on L05-GND "NONET_L-01_P-001" (solid, remove dead copper, pour order 11): -145,3870 4620,3870 4620,-90 -140,-90 -140,3615
P0V95_I225 on L01-TOP "NONET_L-01_P-001" (solid, remove dead copper, pour order 14): 599.57,2761.5 599.57,2817.12 603.44,2820.99 647.99,2820.99 670.43,2798.55 670.43,2761.5
SW_DVDDL on L01-TOP "NONET_L-01_P-001" (solid, remove dead copper, pour order 17): 1834.33,2595.67 1820,2610 1770,2610 1765,2605 1765,2543.62 1783.62,2525 1820,2525 1834.33,2539.33 1834.33,2544.33
GND on L01-TOP "NONET_L-01_P-001" (solid, remove dead copper, pour order 96): -105,1060 -105,3765 35,3905 4535,3905 4645,3795 4645,-30 4575,-100 4555,-80 -110,-80
P2V5 on L01-TOP "NONET_L-01_P-001" (solid, remove dead copper, pour order 95): 438.12,2330.65 463.77,2305 570,2305 580,2295 580,2250 575,2245 400,2245 380,2265
PHY_DVDDL on L01-TOP "NONET_L-01_P-001" (solid, remove dead copper, pour order 93): 2484.25,2220.08 2490.39,2226.22 2603.78,2226.22 2640,2190 2640,2070 2632.28,2062.28 2535.16,2062.28 2535.16,2166.42 2521.58,2180 2500,2180 2500,2184.17 2484.25,2199.92
P1V2 on L01-TOP "NONET_L-01_P-001" (solid, remove dead copper, pour order 77): 2535.16,2460.16 2550,2475 2605,2475 2635,2445 2635,2295 2593.78,2253.78 2536.61,2253.78 2530.47,2259.92 2484.25,2259.92 2484.25,2280.08 2504.17,2300 2514.84,2300 2535.16,2320.31
PHY_DVDDH on L01-TOP "NONET_L-01_P-001" (solid, remove dead copper, pour order 72): 3716.14,511.14 3710,505 3710,460 3745,425 3870.43,425 3920.75,475.31 3920.75,555.91 3909.61,567.05 3889.45,567.05 3869.57,547.17 3869.57,526.5 3854.21,511.14 3814.84,511.14
P3V3 on L01-TOP "NONET_L-01_P-001" (solid, remove dead copper, pour order 71): 4121.14,511.14 4130,520 4160,520 4170,510 4170,455 4155,440 3983.62,440 3948.31,475.31 3948.31,555.91 3959.45,567.05 3984.39,567.05 4000.37,551.06 4000.37,525.61 4014.84,511.14 4054.21,511.14
P3V3 on L01-TOP "NONET_L-01_P-001" (solid, remove dead copper, pour order 68): 3975.08,247.95 3985.07,257.95 3985.07,319.85 3971.06,333.86 3939.84,333.86 3939.84,263.03 3954.92,247.95
PHY_AVDDH on L01-TOP "NONET_L-01_P-001" (solid, remove dead copper, pour order 67): 3915.08,247.95 3930.16,263.03 3930.16,315 3920.38,324.78 3886.61,324.78 3886.61,256.26 3894.92,247.95
PHY_AVDDH on L01-TOP "NONET_L-01_P-001" (solid, remove dead copper, pour order 66): 3930.16,296.14 3867.41,296.14 3864.69,298.86 3741.14,298.86 3720,320 3720,360 3760,400 3905,400 3930,375
P3V3 on L01-TOP "NONET_L-01_P-001" (solid, remove dead copper, pour order 65): 4155,315 4133.86,293.86 4010.31,293.86 4008.04,296.14 3939.84,296.14 3939.84,359.84 3980,400 4125,400 4155,370
P3V3_CM4 on L01-TOP "NONET_L-01_P-001" (solid, remove dead copper, pour order 18): 4256.64,2866.28 4228.72,2866.28 4215,2880 4185,2880 4180,2875 4180,2845 4182.35,2842.65 4256.64,2842.65
P5V on L01-TOP "NONET_L-01_P-001" (solid, remove dead copper, pour order 64): 4364.12,2882.02 4397.02,2882.02 4405,2890 4430,2890 4440,2880 4440,2790 4435,2785 4400,2785 4400,2787.09 4391.68,2795.41 4364.12,2795.41
P1V2 on L01-TOP "NONET_L-01_P-001" (solid, remove dead copper, pour order 63): 351.81,2961.73 351.81,2998.19 325.07,3024.93 124.93,3024.93 120.67,3020.67 120.67,2905 135.89,2905 194.6,2963.71 313.42,2963.71 328.19,2948.94
P2V5 on L01-TOP "NONET_L-01_P-001" (solid, remove dead copper, pour order 62): 259.53,2339.96 270,2350.43 318.82,2350.43 334.92,2334.33 408.03,2334.33 411.71,2330.65 438.29,2330.65 438.29,2278.29 405,2245 327.01,2245 310.71,2261.3 310.71,2279.19 302.57,2287.32 267.4,2287.32 259.53,2295.2
P3V3 on L01-TOP "NONET_L-01_P-001" (solid, remove dead copper, pour order 55): 156.88,2541.29 146.26,2530.67 120.67,2530.67 120.67,2466.97 134.35,2453.29 134.35,2411.4 140.51,2405.24 140.51,2380.51 120,2360 120,2315 143.78,2291.22 192.14,2291.22 200.47,2299.55 200.47,2338.62 219.33,2357.48 219.33,2430.67 240,2451.34 264.82,2451.34 285.4,2471.92 285.4,2541.29
P5V on L01-TOP "NONET_L-01_P-001" (solid, remove dead copper, pour order 51): 124.35,2735 120.67,2738.68 120.67,2820.67 141.34,2841.34 198.87,2841.34 224.02,2816.19 224.02,2776.99 218.12,2771.08 197.45,2771.08 190.91,2777.62 166.93,2777.62 166.93,2731.93 156.71,2721.71 124.35,2721.71
GND on L01-TOP "NONET_L-01_P-001" (solid, remove dead copper, pour order 48): 395.1,3274.74 395.1,3335.57 399.8,3340.28 454.72,3340.28 462.6,3332.4 462.6,3252.6 450,3240 419.98,3240 394.53,3265.45
P5V on L01-TOP "NONET_L-01_P-001" (solid, remove dead copper, pour order 47): 319.46,3340.56 335.47,3324.55 335.47,3206.14 315.67,3186.34 274.33,3186.34 218.35,3242.32 218.35,3269.44 186.78,3269.44 186.78,3340.56
NetC17_1 on L01-TOP "NONET_L-01_P-001" (solid, remove dead copper, pour order 45): 1106.06,1491.34 1100.24,1485.51 1063.99,1485.51 1053.24,1474.76 1026.76,1474.76 1018.89,1482.63 1018.89,1511.25 1034.35,1526.71 1034.35,1567.22 1030.71,1570.87 1030.71,1606.3 1119.29,1606.3 1119.29,1559.13 1106.06,1545.91
P3V3 on L01-TOP "NONET_L-01_P-001" (solid, remove dead copper, pour order 44): 1113.94,1545.91 1139.76,1571.73 1139.76,1590.24 1175.92,1590.24 1194.08,1572.07 1194.08,1521.76 1156.67,1484.35 1121.71,1484.35 1113.94,1492.13 1113.94,1534.09
NetC23_1 on L01-TOP "NONET_L-01_P-001" (solid, remove dead copper, pour order 43): 2834.42,1663.4 2834.42,1639.06 2845.24,1628.24 2845.24,1594.76 2830.93,1580.44 2830.93,1553.87 2812.77,1535.71 2718.7,1535.71 2718.7,1624.29 2768.4,1624.29 2774.57,1618.12 2795.04,1618.12 2795.04,1620.3 2802.13,1627.39 2802.13,1642.93 2822.61,1663.4
P3V3 on L01-TOP "NONET_L-01_P-001" (solid, remove dead copper, pour order 36): 2797.73,1671.28 2797.01,1670.55 2776.54,1670.55 2776.54,1705.69 2782.56,1711.71 2782.56,1772.56 2795,1785 2855,1785 2860.24,1779.76 2860.24,1680.24 2851.28,1671.28
SW_AVDDH on L01-TOP "NONET_L-01_P-001" (solid, remove dead copper, pour order 35): 556.02,2314.69 542.64,2328.06 519.76,2328.06 519.76,2374.52 530.67,2385.43 530.67,2455.67 545,2470 625,2470 625,2431.61 620.53,2427.14 620.53,2331.35 603.86,2314.69
P2V5 on L01-TOP "NONET_L-01_P-001" (solid, remove dead copper, pour order 34): 535.67,2164.33 550,2150 610,2150 625,2165 625,2283.86 603.86,2305 536.54,2305 519.76,2288.23 519.76,2248.74 535.67,2232.83
P3V3 on L01-TOP "NONET_L-01_P-001" (solid, remove dead copper, pour order 33): 1503.23,3042.27 1503.23,3148.23 1540,3185 1605,3185 1615,3175 1615,3144.16 1610.51,3139.67 1610.51,3104.24 1622.36,3092.39 1629.06,3092.39 1658.93,3062.51 1661.73,3062.51 1661.73,3042.35 1660.59,3041.21 1570,3041.21 1568.94,3042.27
SW_VDDIO on L01-TOP "NONET_L-01_P-001" (solid, remove dead copper, pour order 32): 1661.73,3007.51 1655.59,3013.65 1500.24,3013.65 1498.23,3011.64 1498.23,2911.77 1520,2890 1586.27,2890 1605.51,2909.24 1605.51,2944.67 1619.32,2958.48 1653.48,2958.48 1661.73,2966.73 1661.73,2987.35
P2V5 on L01-TOP "NONET_L-01_P-001" (solid, remove dead copper, pour order 31): 1938.3,2902.95 1938.3,2936.06 1928.23,2946.14 1928.23,2983.86 1959.36,3015 2120,3015 2140,2995 2140,2975 2113.86,2948.86 1998.7,2948.86 1988.86,2939.02 1988.86,2905 1960.51,2905 1958.46,2902.95
SW_VDDHS on L01-TOP "NONET_L-01_P-001" (solid, remove dead copper, pour order 30): 1743.86,2953.86 1735,2945 1720,2945 1710,2955 1710,2990 1730,3010 1910,3010 1918.54,3001.46 1918.54,2918.03 1903.46,2902.95 1878.01,2902.95 1857.91,2923.05 1857.91,2944.02 1848.07,2953.86 1786.1,2953.86
SW_VDDLS on L01-TOP "NONET_L-01_P-001" (solid, remove dead copper, pour order 29): 2195.16,2846.97 2180.08,2862.05 2159.92,2862.05 2159.92,2861.25 2134.53,2835.86 2134.53,2815.98 2124.69,2806.14 2027.28,2806.14 2018.43,2815 1995,2815 1985,2805 1985,2770 2005,2750 2169.02,2750 2195.16,2776.14
P1V2 on L01-TOP "NONET_L-01_P-001" (solid, remove dead copper, pour order 28): 2418.86,2806.14 2430,2795 2430,2755 2425,2750 2230.98,2750 2204.84,2776.14 2204.84,2846.97 2219.92,2862.05 2240.08,2862.05 2265.47,2836.66 2265.47,2815.98 2275.31,2806.14 2337.28,2806.14
P1V2 on L01-TOP "NONET_L-01_P-001" (solid, remove dead copper, pour order 27): 2314.25,2604.69 2354.57,2645 2490.3,2645 2540,2595.3 2540,2570 2535,2565 2492.05,2565 2478.19,2578.86 2380.79,2578.86 2365.43,2563.5 2365.43,2537.83 2340.55,2512.95 2320.39,2512.95 2314.25,2519.09 2314.25,2565.31
SW_DVDDL on L01-TOP "NONET_L-01_P-001" (solid, remove dead copper, pour order 26): 2286.69,2519.09 2280.55,2512.95 2255.5,2512.95 2230,2538.46 2230,2560.59 2220.16,2570.43 2160.24,2570.43 2158.19,2572.48 2117.48,2572.48 2100,2555 2075,2555 2065,2565 2065,2629.32 2069.99,2634.31 2267.25,2634.31 2286.69,2614.87
PHY_AVDDL on L01-TOP "NONET_L-01_P-001" (solid, remove dead copper, pour order 25): 2259.93,2439.47 2273.96,2453.51 2343.51,2453.51 2365,2475 2460,2475 2475,2460 2475,2425 2459.47,2409.47 2392.36,2409.47 2387.36,2404.47 2330.4,2404.47 2320.55,2394.62 2320.55,2380.63 2317.23,2380.63 2295.16,2358.56 2259.93,2360
P1V2 on L01-TOP "NONET_L-01_P-001" (solid, remove dead copper, pour order 24): 2240.16,2358.56 2250.24,2368.64 2250.24,2439.47 2224.71,2465 2050,2465 2040,2455 2040,2415 2050.53,2404.47 2179.77,2404.47 2189.61,2394.62 2189.61,2368.59 2199.64,2358.56 2220,2358.56
SW_AVDDL on L01-TOP "NONET_L-01_P-001" (solid, remove dead copper, pour order 23): 2245.16,2283.86 2228.66,2300.36 2060.36,2300.36 2035,2275 2035,2240 2045,2230 2065.01,2230 2072.28,2237.27 2072.28,2248.86 2174.69,2248.86 2187.25,2236.29 2191.77,2236.29 2191.77,2226.1 2214.92,2202.95 2235.08,2202.95 2245.16,2213.03 2245.16,2246.14
P1V2 on L01-TOP "NONET_L-01_P-001" (solid, remove dead copper, pour order 22): 2422.72,2248.86 2430,2256.14 2430,2310 2420,2320 2320,2320 2293.71,2293.71 2264.69,2293.71 2254.84,2283.86 2254.84,2218.03 2269.92,2202.95 2296.49,2202.95 2315.47,2221.94 2315.47,2242.44 2325.31,2252.28 2383.86,2252.28 2387.28,2248.86
PHY_AVDDL_PLL on L01-TOP "L01-TOP-PHY_AVDDL_PLL" (solid, remove dead copper, pour order 20): 3454.63,1835 3480.16,1860.53 3480.16,1908.49 3480.16,1946.44 3444.92,1946.44 3426.77,1928.29 3426.77,1908.1 3421.37,1902.7 3344.88,1902.7 3342.72,1900.53 3307.28,1900.53 3297.82,1910 3260,1910 3257.48,1907.48 3257.48,1850.47 3272.95,1835
P1V2 on L01-TOP "NONET_L-01_P-001" (solid, remove dead copper, pour order 19): 3489.84,1860.53 3520.37,1830 3680,1830 3710,1860 3710,1900 3700,1910 3662.18,1910 3657.72,1905.53 3545.8,1905.53 3535,1916.33 3535,1931.52 3520.08,1946.44 3499.92,1946.44 3489.84,1936.36 3489.84,1898.25
GND on L06-BOT "NONET_L-01_P-001" (solid, remove dead copper, pour order 94): -95,3895 4490,3895 4790,3595 4790,105 4530,-155 -150,-155
SW_DVDDL on L06-BOT "NONET_L-01_P-001" (solid, remove dead copper, pour order 91): 2120.65,2623.06 1641.61,2623.06 1598.47,2579.93 1598.47,2411.53 1754.67,2255.33 2032.34,2255.33 2200.21,2423.2 2200.21,2552.72
P1V2 on L06-BOT "NONET_L-01_P-001" (solid, remove dead copper, pour order 52): 124.35,2908.93 128.28,2905 164.62,2905 185,2925.38 185,3035.69 172.41,3048.29 124.35,3048.29
P3V3 on L06-BOT "NONET_L-01_P-001" (solid, remove dead copper, pour order 50): 134.76,2376.76 134.76,2426.3 134.35,2426.71 134.35,2453.29 149.72,2468.66 195.22,2468.66 220.65,2443.24 220.65,2358.8 204.29,2342.44 142.56,2342.44 130,2355 130,2374.25 135,2379.25
P2V5 on L06-BOT "NONET_L-01_P-001" (solid, remove dead copper, pour order 49): 258.19,2311.06 311.34,2311.06 334.76,2334.49 417.49,2334.49 418.24,2335.24 418.24,2307.08 371.16,2260 283.66,2260 258.19,2285.47
P5V on L06-BOT "NONET_L-01_P-001" (solid, remove dead copper, pour order 46): 132.87,2819.84 125.51,2827.2 125.51,2870.24 134.95,2879.68 185.23,2879.68 209.51,2855.39 209.51,2803.37 191.54,2785.4 174.72,2785.4 166.93,2777.62 166.93,2754.77 160.42,2748.27 139.76,2748.27 132.87,2755.16
P5V on L06-BOT "NONET_L-01_P-001" (solid, remove dead copper, pour order 42): 299.76,3192.01 288.29,3203.48 251.52,3203.48 219.76,3235.24 219.76,3260.24 403.26,3260.24 413.78,3249.72 413.78,3218.78 387.01,3192.01
P5V on L06-BOT "NONET_L-01_P-001" (solid, remove dead copper, pour order 41): 219.76,3294.3 225.51,3300.05 225.51,3335.24 235,3344.72 235,3448.52 256.3,3469.82 312.71,3469.82 327.17,3455.37 409.63,3455.37 413.78,3451.22 413.78,3350.47 413.78,3249.72 230.28,3249.72 219.76,3260.24
SFP1_VCCR on L06-BOT "NONET_L-01_P-001" (solid, remove dead copper, pour order 37): 764.5,1544.31 741.62,1544.31 736.69,1549.23 679.89,1549.23 647.32,1581.8 647.32,1729.26 652.45,1734.39 672.45,1734.39 677.45,1729.39 677.45,1717.15 708.74,1685.86 708.82,1685.86 708.82,1650.42 730.17,1629.07 778.59,1629.07 778.59,1578.56 764.5,1564.47
SFP1_VCCT on L06-BOT "NONET_L-01_P-001" (solid, remove dead copper, pour order 38): 620.31,1550.56 566.11,1550.56 558.98,1543.43 536.1,1543.43 536.1,1572.96 524.48,1584.58 524.48,1620.01 554.01,1620.01 564,1630.01 564,1680.4 589.32,1705.72 605.14,1705.72 605.14,1725.72 615.14,1735.72 635.14,1735.72 640.14,1730.72 640.14,1570.4
P3V3 on L06-BOT "NONET_L-01_P-001" (solid, remove dead copper, pour order 39): 520.7,1432.71 578.97,1432.71 583.97,1437.71 651.8,1437.71 654.32,1435.19 715.15,1435.19 717.67,1437.71 761.53,1437.71 775.39,1423.85 800.39,1423.85 810.39,1433.85 810.39,1458.85 795.39,1473.85 770.39,1473.85 762.44,1481.81 762.44,1523.93 747.36,1539.01 582.82,1539.01 562.75,1518.93 537.73,1518.93 537.73,1485.17 520.7,1468.14 521.69,1467.16 521.69,1423.85
PHY_DVDDH on L03-SIG "NONET_L-01_P-001" (solid, remove dead copper, pour order 84): 2393.67,1910.62 2393.67,1943.05 2364.19,1972.52 2245.87,1972.52 2145,1871.65 2145,1753.39 2206.99,1691.4 2206.99,1664.63 2192.71,1650.35 2192.71,1607.29 2226.94,1573.06 2294.09,1573.06 2294.09,1617.23 2300.87,1624 2391.13,1624 2391.13,1554 2601,1554 2850,1305 3575,1305 3575,765 3575,677.29 3747.34,504.94 3747.34,452.13 3700.22,405 3641.94,405 2881.94,1165 2660,1165 2660,1248.4 2528.4,1380 2273.6,1380 2085.81,1567.8 2085.81,1961.13 2165.05,2040.38 2408.73,2040.38 2432.8,2016.31 2432.8,1931.1 2412.28,1910.59
SW_DVDDL on L03-SIG "NONET_L-01_P-001" (solid, remove dead copper, pour order 92): 2120,2610 2120,2526.59 2045.27,2451.86 2045.27,2291.08 1889.92,2135.73 1889.92,2097.05 1661.47,1868.59 1661.47,1798.12 1618.54,1755.19 1579.95,1755.19 1537.73,1797.42 1429.74,1797.42 1392.34,1760.01 1345.58,1760.01 1288.53,1817.06 1288.53,1861.7 1156.48,1993.76 1156.48,2093.6 1089.89,2160.19 1069.81,2160.19 1037.43,2192.57 1037.43,2302.43 1047.61,2312.61 1149.19,2312.61 1210,2373.42 1210,2526.99 1273.39,2590.38 1375.02,2590.38 1388.42,2576.98 1388.42,2439.47 1273.39,2324.44 1273.39,2041.61 1395,1920 1495,1920 1751.46,2176.46 1751.46,2201.13 1836.69,2286.37 1919.3,2286.37 1987.17,2354.24 1987.17,2435.72 2079.21,2527.76 2079.21,2631.86 2081.66,2634.31 2082.23,2633.74 2119.68,2633.74
SW_AVDDL on L03-SIG "NONET_L-01_P-001" (solid, remove dead copper, pour order 90): 1994.88,2239.88 1994.88,2141.17 1933.94,2080.22 1879.65,2080.22 1834.92,2035.5 1834.92,1988.02 1823.48,1976.58 1771.58,1976.58 1672.15,1877.15 1672.15,1788.32 1624.13,1740.3 1584.7,1740.3 1531.99,1793.01 1430.56,1793.01 1393.84,1756.29 1328.25,1756.29 1275.27,1809.27 1275.27,1859.96 1171.71,1963.51 1162.15,1963.51 1150.82,1974.85 1150.82,2023.65 1111.16,2063.31 1111.16,2132.98 1103.6,2140.54 1041.62,2140.54 980,2078.92 980,2040 981.34,2040 1001.26,2020.08 1076.53,2020.08 1086.18,2010.43 1086.18,1985.04 1080.1,1978.95 1080.1,1954.61 1101.5,1933.2 1112.2,1933.2 1130,1915.41 1130,1833.14 1284.37,1678.77 1718.77,1678.77 2120,2080 2120,2280 2115,2285 2040,2285
SW_VDDLS on L03-SIG "NONET_L-01_P-001" (solid, remove dead copper, pour order 89): 1742.34,2681.81 1677.65,2681.81 1621.95,2626.11 1621.95,2575.19 1567.15,2520.39 1442.12,2520.39 1419.63,2542.88 1394.4,2542.88 1388.42,2536.9 1388.42,2505.47 1548.89,2345 1685,2345 1738.17,2291.83 1921.83,2291.83 1985,2355 1985,2437.3 2077.39,2529.69 2077.39,2793.4 2046.93,2823.86 1983.86,2823.86 1975,2815 1975,2749.93 2012.48,2712.44 2012.48,2521.35 1935,2443.87 1935,2360.83 1898.99,2324.82 1844.73,2324.82 1764.55,2405 1704.21,2405 1634.99,2474.21 1634.99,2544.08 1675.47,2584.56 1675.47,2620.19 1694.48,2639.2 1748.46,2639.2 1757.7,2648.45 1757.7,2671.29
SW_VDDHS on L03-SIG "NONET_L-01_P-001" (solid, remove dead copper, pour order 88): 1556.88,2875 1590,2875 1598.31,2883.31 1598.31,2958.31 1643.61,3003.61 1744.33,3003.61 1761.6,2986.34 1761.6,2706.21 1740.01,2684.62 1676.71,2684.62 1619.93,2627.84 1619.93,2574.93 1597.46,2552.46 1597.46,2544.79 1588.46,2535.79 1580.22,2535.79 1573.19,2528.77 1436.23,2528.77 1396.04,2568.96 1396.04,2714.16
SW_VDDIO on L03-SIG "NONET_L-01_P-001" (solid, remove dead copper, pour order 87): 1055,2420 1055,2564.23 1680.77,3190 1730.31,3190 1960.51,2959.79 1960.51,2752.16 2005.14,2707.53 2005.14,2520.31 1931.7,2446.87 1931.7,2359.84 1901.49,2329.63 1848.79,2329.63 1758.42,2420 1709.94,2420 1640.32,2489.61 1640.32,2549.41 1685.32,2594.41 1685.32,2621.81 1697.82,2634.31 1758.8,2634.31 1769.18,2644.69 1769.18,2990.82 1750,3010 1629.24,3010 1586.27,2967.04 1586.27,2890 1560.36,2890 1200.36,2530 1200.36,2380.13 1140.92,2320.69 1086.29,2320.69 1055.55,2351.42 1055.55,2360.61
SW_AVDDH on L03-SIG "NONET_L-01_P-001" (solid, remove dead copper, pour order 85): 1292.09,1655.1 1188.4,1758.79 1086.72,1860.47 1086.72,1879.32 1112.31,1904.91 1112.31,1921.06 1098.38,1935 1075,1935 1075,1980 1085,1990 1085,2008.97 1076.62,2017.35 1060.2,2017.35 1050,2007.15 972.85,2007.15 955,2025 955,2107.76 1005,2157.76 1005,2220 889.68,2220 795,2125.32 795,2055.38 985.38,1865.01 985.38,1741.26 1087.44,1639.19 1292.03,1639.19
PHY_DVDDL on L03-SIG "NONET_L-01_P-001" (solid, remove dead copper, pour order 69): 2535.16,2114.35 2621.11,2114.35 2630.47,2105 2630.47,1975.47 2592.5,1937.5 2525.09,1937.5 2495.75,1966.84 2495.75,2095.93 2513.75,2113.93
P3V3 on L03-SIG "NONET_L-01_P-001" (solid, remove dead copper, pour order 73): 52.49,2411.67 52.49,582.51 600.41,34.59 3575,34.59 3575,270 1210,270 310.71,1169.29 310.71,2410 199,2410
P1V2 on L03-SIG "NONET_L-01_P-001" (solid, remove dead copper, pour order 74): 2360,2815 2360,2679.5 2478.19,2561.31 2478.19,2526.49 2610,2394.68 2794.68,2394.68 2825,2425 2825,2791.75 2772.85,2843.91 2381.56,2843.91 2361.51,2823.86
P1V2 on L03-SIG "NONET_L-01_P-001" (solid, remove dead copper, pour order 75): 2711.95,2843.91 3756.09,2843.91 3855,2745 3855,1800 3805,1750 3530,1750 3270,2010 3270,2150 3026.85,2393.15 2737.85,2393.15
P1V2 on L03-SIG "NONET_L-01_P-001" (solid, remove dead copper, pour order 76): 2046.49,2451.22 2046.49,2395.69 2232.18,2210 2442.07,2210 2442.07,2404.29 2424.76,2421.61 2424.76,2459.76 2450,2485 2554.56,2485 2574.78,2505.22 2574.78,2715.22 2485,2805 2205.18,2805 2120.65,2720.47 2120.65,2513.34
P1V2 on L03-SIG "NONET_L-01_P-001" (solid, remove dead copper, pour order 78): 95,2851.29 95,3006.06 137.22,3048.29 188.29,3048.29 245,3105 245,3705 315,3775 2545,3775 2680,3640 2680,2714.02 2660.6,2694.62 2260.38,2694.62 2200,2755 2200,3460 2165,3495 780,3495 575,3290 575,2955 466.92,2846.92
P2V5 on L03-SIG "NONET_L-01_P-001" (solid, remove dead copper, pour order 79): 323.05,2322.78 323.05,2156.95 390,2090 630,2090 685,2145 685,2295 630,2350 327.8,2350 323.19,2345.39
P2V5 on L03-SIG "NONET_L-01_P-001" (solid, remove dead copper, pour order 80): 2180,2965 2180,3250 2020,3410 815,3410 321.01,2916.01 321.01,2510.68 321.01,2183.99 395,2110 747.1,2110 1055.28,2418.17 1055.28,2578.54 1671.73,3195 1738.11,3195 1967.99,2965.12 2096.1,2965.12
PHY_AVDDL on L03-SIG "NONET_L-01_P-001" (solid, remove dead copper, pour order 81): 2427.8,2423.67 2605,2246.46 2605,1928.04 2491.32,1814.36 2491.32,1701.65 2511.52,1681.45 2543.3,1681.45 2562.95,1701.1 2562.95,1732.95 2805,1975 2805,2190.14 2520.14,2475 2445.67,2475 2427.97,2457.3
PHY_AVDDH on L03-SIG "NONET_L-01_P-001" (solid, remove dead copper, pour order 82): 2555,1920 2505,1920 2405,1820 2405,1674.49 2454.49,1625 2630,1625 2750,1745 2750,1795 2840,1885 3277.89,1885 3585,1577.89 3585,670 3750,505 3750,445 3695,390 3695,325 3735,285 3815,285 3895,365 3895,735 3740,890 3740,1535 3295,1980 2818.68,1980 2571.58,1732.9 2571.58,1702.21 2546.37,1677 2509.23,1677 2484.02,1702.21 2484.02,1813.2 2554.77,1883.95 2554.77,1891.46
PHY_DVDDL on L03-SIG "NONET_L-01_P-001" (solid, remove dead copper, pour order 83): 2402.6,1910.75 2586.85,2095 2605,2095 2605,1950 2580,1925 2505.54,1925 2400.54,1820 2361.82,1820 2295.94,1754.12 2296.37,1753.7 2296.37,1573.06 2226.94,1573.06 2192.71,1607.29 2192.71,1650.35 2208.78,1666.42 2208.78,1689.61 2145,1753.39 2145,1875 2242.52,1972.52 2364.19,1972.52 2393.67,1943.05 2393.67,1910.62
